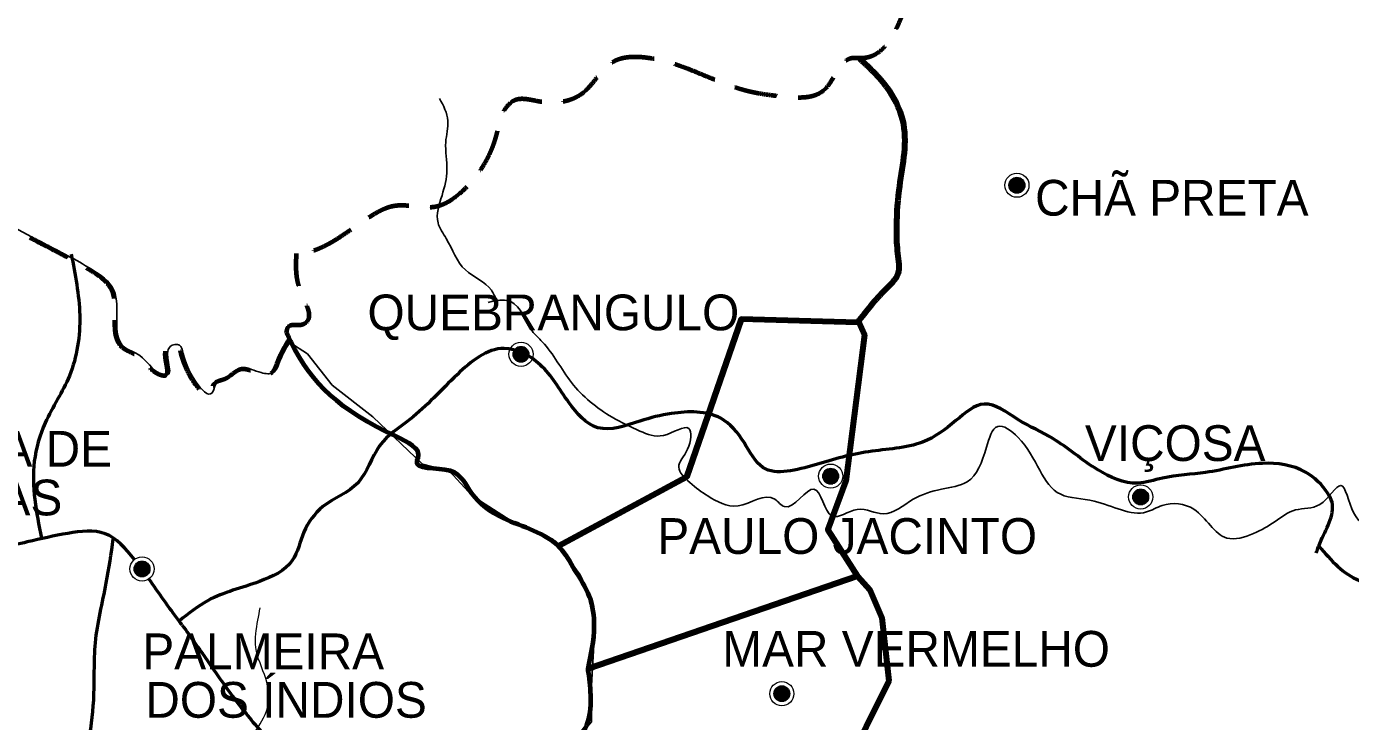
# Model space of a CAD drawing. Extents: x 512883 to 1063249, y 8784064 to 9081064.
# Drawn here: x 755485 to 811055, y 8952193 to 8981350 of the extents above; entities that cross this region are included whole.
import ezdxf

# ---------------------------------------------------------------- set-up
doc = ezdxf.new("R2010")
doc.units = 0
doc.header["$LTSCALE"] = 600
doc.linetypes.add('MEDIUM_DASHED', pattern=[4.5, 3, -1.5])
for name, color, linetype, lineweight in [('10', 7, 'Continuous', 53), ('13', 7, 'Continuous', 90), ('20', 7, 'Continuous', 53), ('5', 7, 'Continuous', 13), ('60', 7, 'Continuous', 25), ('7', 7, 'Continuous', 13)]:
    doc.layers.add(name, color=color, linetype=linetype, lineweight=lineweight)

msp = doc.modelspace()

# ---------------------------------------------------------------- linework, layer by layer
at = {"layer": '10'}
for points in [[(809616.9, 8959267.4), (809825.5, 8959797.2), (810249, 8961488.9), (810105.3, 8961759.7), (809170.8, 8962654), (807357.9, 8963023.8), (804970.4, 8962640.4), (803164.1, 8962405.1), (802121.3, 8962193), (800446.9, 8962751), (798563.3, 8964059.7), (797087.1, 8964868.8), (795673.1, 8965511.1), (794494.9, 8964818.7), (793098, 8963916.8), (790831.3, 8963513), (788586.3, 8962963.2), (786396.8, 8962851.7), (785601.5, 8963892.6), (784625.4, 8964912), (782553, 8965114), (781230, 8964796.7), (779464.4, 8964519.7), (778246.8, 8965580), (777043.4, 8967162.2), (775528.5, 8967845.9), (773570.9, 8966754.4), (771581.8, 8964869.9), (770307.8, 8963759.7), (769400.4, 8962212.5), (767924.2, 8961206.1), (767132.1, 8960139.2), (766642.8, 8958948.2), (765265.7, 8958067.2), (763103.9, 8957267.3), (761887.4, 8956407.7)], [(760025.4, 8958989.5), (758791.9, 8960070.6), (757224, 8960086.4), (755519.6, 8959726.1), (753291.3, 8959489.3), (750147.9, 8960209.6), (749997.5, 8960195.6)], [(760373.1, 8942504.5), (759520.9, 8943232.2), (758173.4, 8945126.8), (757857.6, 8946419.7), (757806.3, 8949236.7), (758306.2, 8953099), (758380.2, 8955499.1), (758834.8, 8958004.7), (759126.7, 8959859.4)], [(809734.3, 8959555), (811432, 8958112), (812579.6, 8957927.9), (814085.6, 8958058), (814804.3, 8958498.5), (816229.1, 8958691), (817376.8, 8958506.8), (818165.9, 8958029.4), (818881.1, 8956967.5), (819268.1, 8956509.6), (820335.8, 8956283.5), (821302.8, 8956077.9), (822492.5, 8955727), (823556.6, 8954019.2), (824559.4, 8952394.8), (826374, 8950063.4), (827121.3, 8946706.5), (827050.8, 8944306.1)], [(762022.2, 8956228.6), (761887.4, 8956407.7), (760623.2, 8958172.3)]]:
    msp.add_spline(points, degree=3, dxfattribs=at)
at = {"layer": '13'}
msp.add_line((790366.5, 8958294.4), (779053.8, 8954397.2), dxfattribs=at)
for points in [[(790369.3, 8968937.3), (785483.9, 8969067.6), (783185.5, 8962444.9), (777810.8, 8959546.7)], [(790399.5, 8968972.9), (790656.5, 8968416.5), (789880.2, 8962278.7), (789119.1, 8960231.1), (790366.5, 8958294.4), (790875.4, 8957711.7), (791390.8, 8956544.8), (791681.4, 8953895.4), (789774.1, 8950070.4), (790016.3, 8949759.2)]]:
    msp.add_lwpolyline(points, dxfattribs=at)
at = {"layer": '13', "lineweight": 25}
msp.add_lwpolyline([(787332.9, 8950099.2), (785823.8, 8950099.2), (783836.6, 8949815), (781186.9, 8949530.8), (779767.4, 8949720.3), (778537.2, 8949909.7), (777401.6, 8949909.7), (777874.8, 8950667.6), (778726.4, 8951614.9), (779199.6, 8952183.3), (779199.6, 8953699), (779294.2, 8955404.1), (779294.2, 8957014.5), (778726.4, 8958340.8), (777685.5, 8959761.7), (775982.1, 8960519.6), (774184.1, 8961656.3), (773237.8, 8962698.4), (772102.2, 8962982.6), (770020.3, 8964971.9), (768316.9, 8966298.1), (767276, 8967624.4), (766531.3, 8968098.7)], dxfattribs=at)
at = {"layer": '13', "linetype": 'MEDIUM_DASHED', "lineweight": 70}
for points in [[(794561.3, 8984247.3), (793616.3, 8984286), (792392.4, 8982278.7), (790528.1, 8980018.9), (790126.1, 8980017.6), (788955.1, 8978678.2), (787269.9, 8978401.5), (785639, 8978667.5), (783741.9, 8979370.9), (781684.8, 8980011.2), (780098.6, 8979860), (778786.9, 8978520.2), (777001.7, 8978201.4), (775996.1, 8978260.7), (775361.7, 8977465.7), (775246.4, 8976985.3), (773727.5, 8974392.8), (772648.9, 8973784.1), (770940.2, 8973820.3), (769920, 8973378.8), (768383.8, 8972351.3), (766882.2, 8971824.7), (766821.9, 8971824.5)], [(753258.6, 8973800.6), (756145, 8972228.3), (758126.6, 8971149.5), (759060.8, 8970276.1), (759489.1, 8967898.4), (760156.5, 8967525), (761008.9, 8966776.5), (761311.1, 8966714.8), (761418.5, 8967904.7), (761819.8, 8967968.6), (761964.4, 8967614.3), (763228, 8966032.4), (763365, 8966366.7), (763825, 8966576.9), (764463.7, 8966975.4), (765249.4, 8966811), (765751.8, 8966812.7), (766047.5, 8967335.3), (766506.4, 8968208.9)], [(766401.5, 8968517.5), (766493.8, 8968776.7), (767015.7, 8968841), (767255.5, 8968966.9), (767000.5, 8970218.2), (766821.9, 8971824.5)]]:
    msp.add_spline(points, degree=3, dxfattribs=at)
at = {"layer": '13'}
msp.add_spline([(790464.2, 8979989.1), (791688.7, 8978666.2), (792287.2, 8977249.1), (792096.9, 8974473), (791995.2, 8972761.4), (792045.8, 8971822.5), (792055.3, 8970966.9), (791539.9, 8970318.3), (790369.3, 8968937.3)], degree=3, dxfattribs=at)
at = {"layer": '13', "lineweight": 25}
msp.add_spline([(766531.3, 8968098.7), (766139.1, 8967352), (765843.4, 8966829.4), (765340.9, 8966827.7), (764555.2, 8966992.2), (763916.5, 8966593.6), (763456.6, 8966383.4), (763319.6, 8966049.1), (762055.9, 8967631), (761911.3, 8967985.3), (761510.1, 8967921.4), (761402.6, 8966731.5), (761100.5, 8966793.2), (760248, 8967541.7), (759580.7, 8967915.2), (759152.4, 8970292.8), (758218.2, 8971166.2), (756236.6, 8972245), (753350.1, 8973817.3)], degree=3, dxfattribs=at)
at = {"layer": '13', "lineweight": 70}
for points in [[(779053.8, 8954397.2), (779315.4, 8956192.7), (779120.9, 8957423.3), (778505.5, 8958548.2), (777872, 8959485.3), (775486.6, 8960729.7), (774168.7, 8961768.8), (773274, 8962705), (771882.4, 8963138.8), (771921.4, 8963243.2), (770966.7, 8964158.3), (766602, 8968088.4), (766401.5, 8968517.5)], [(777083.3, 8949780.2), (777094.8, 8949799.9), (777707.5, 8950740.9), (778940.6, 8951913.5), (779169.6, 8953020.3), (779097.1, 8954126.1), (779053.8, 8954397.2)]]:
    msp.add_spline(points, degree=3, dxfattribs=at)
at = {"layer": '20'}
for points in [[(757362.8, 8971798.3), (757718.1, 8969235), (757286.6, 8966697.4), (756271.3, 8964723.6), (755814.4, 8963108.8), (756109.2, 8959887.7)], [(762022.2, 8956228.6), (763065.5, 8954766.9), (764487.8, 8952789.5), (765663, 8951394.6), (767135.2, 8949600.3), (768531.3, 8947190.8), (769724.3, 8944935.2), (771450.3, 8942705.1), (774169.2, 8941219.5), (776144.1, 8941290.1)]]:
    msp.add_spline(points, degree=3, dxfattribs=at)
at = {"layer": '5'}
for p, q in [((796721.7, 8974699.1), (797386.5, 8974699.1)), ((796722.3, 8974669.1), (797386.2, 8974669.1)), ((796723.8, 8974729.1), (797384.4, 8974729.1)), ((796725.3, 8974639.1), (797382.9, 8974639.1)), ((796728.6, 8974759.1), (797379.6, 8974759.1)), ((796731.3, 8974609.1), (797376.9, 8974609.1)), ((796736.7, 8974789.1), (797371.5, 8974789.1)), ((796747.5, 8974819.1), (797360.7, 8974819.4)), ((796761.9, 8974849.1), (797346.6, 8974849.1)), ((796780.2, 8974879.1), (797328.3, 8974879.1)), ((796804.2, 8974909.1), (797304.6, 8974909.1)), ((796833.3, 8974939.1), (797274.9, 8974939.1)), ((796872.9, 8974969.1), (797235.3, 8974969.1)), ((796930.2, 8974999.1), (797178, 8974999.1)), ((796740.3, 8974579.1), (797367.9, 8974579.1)), ((796752.9, 8974549.1), (797355.6, 8974549.4)), ((796768.8, 8974519.1), (797339.4, 8974519.1)), ((796789.5, 8974489.1), (797319, 8974489.4)), ((796814.7, 8974458.8), (797293.8, 8974459.1)), ((796848, 8974429.1), (797260.2, 8974429.1)), ((796893, 8974399.1), (797215.2, 8974399.1)), ((796966.8, 8974369.1), (797141.1, 8974369.1)), ((775908.5, 8967607.6), (776573.2, 8967607.6)), ((775909.1, 8967577.6), (776573, 8967577.6)), ((775910.6, 8967637.6), (776571.2, 8967637.6)), ((775912.1, 8967547.6), (776569.7, 8967547.6)), ((775915.3, 8967667.6), (776566.3, 8967667.6)), ((775918.1, 8967517.6), (776563.7, 8967517.6)), ((775923.5, 8967697.6), (776558.2, 8967697.6)), ((775927.1, 8967487.6), (776554.7, 8967487.6)), ((775934.2, 8967727.6), (776547.5, 8967727.9)), ((775939.7, 8967457.6), (776542.3, 8967457.9)), ((775948.7, 8967757.6), (776533.3, 8967757.6)), ((775955.6, 8967427.6), (776526.2, 8967427.6)), ((775967, 8967787.6), (776515.1, 8967787.6)), ((775976.2, 8967397.6), (776505.8, 8967397.9)), ((775991, 8967817.6), (776491.3, 8967817.6)), ((776020.1, 8967847.6), (776461.7, 8967847.6)), ((776059.7, 8967877.6), (776422.1, 8967877.6)), ((776117, 8967907.6), (776364.8, 8967907.6)), ((776001.5, 8967367.3), (776480.6, 8967367.6)), ((776034.8, 8967337.6), (776447, 8967337.6)), ((776079.8, 8967307.6), (776402, 8967307.6)), ((776153.6, 8967277.6), (776327.8, 8967277.6)), ((788905.1, 8962495.8), (789569.9, 8962495.8)), ((788905.7, 8962465.8), (789569.6, 8962465.8)), ((788907.2, 8962525.8), (789567.8, 8962525.8)), ((788908.7, 8962435.8), (789566.3, 8962435.8)), ((788912, 8962555.8), (789563, 8962555.8)), ((788914.7, 8962405.8), (789560.3, 8962405.8)), ((788920.1, 8962585.8), (789554.9, 8962585.8)), ((788930.9, 8962615.8), (789544.1, 8962616.1)), ((788945.3, 8962645.8), (789530, 8962645.8)), ((788963.6, 8962675.8), (789511.7, 8962675.8)), ((788987.6, 8962705.8), (789488, 8962705.8)), ((789016.7, 8962735.8), (789458.3, 8962735.8)), ((789056.3, 8962765.8), (789418.7, 8962765.8)), ((789113.6, 8962795.8), (789361.4, 8962795.8)), ((788923.7, 8962375.8), (789551.3, 8962375.8)), ((788936.3, 8962345.8), (789539, 8962346.1)), ((788952.2, 8962315.8), (789522.8, 8962315.8)), ((788972.9, 8962285.8), (789502.4, 8962286.1)), ((788998.1, 8962255.5), (789477.2, 8962255.8)), ((789031.4, 8962225.8), (789443.6, 8962225.8)), ((789076.4, 8962195.8), (789398.6, 8962195.8)), ((789150.2, 8962165.8), (789324.5, 8962165.8)), ((801999.5, 8961832.5), (802499.8, 8961832.5)), ((802028.6, 8961862.5), (802470.2, 8961862.5)), ((802068.2, 8961892.5), (802430.6, 8961892.5)), ((802125.5, 8961922.5), (802373.2, 8961922.5)), ((801917, 8961622.5), (802581.8, 8961622.5)), ((801917.6, 8961592.5), (802581.5, 8961592.5)), ((801919.1, 8961652.5), (802579.7, 8961652.5)), ((801920.6, 8961562.5), (802578.2, 8961562.5)), ((801923.8, 8961682.5), (802574.8, 8961682.5)), ((801926.6, 8961532.5), (802572.2, 8961532.5)), ((801932, 8961712.5), (802566.8, 8961712.5)), ((801935.6, 8961502.5), (802563.2, 8961502.5)), ((801942.8, 8961742.5), (802556, 8961742.8)), ((801948.2, 8961472.5), (802550.8, 8961472.8)), ((801957.2, 8961772.5), (802541.8, 8961772.5)), ((801964.1, 8961442.5), (802534.7, 8961442.5)), ((801975.5, 8961802.5), (802523.6, 8961802.5)), ((801984.8, 8961412.5), (802514.2, 8961412.8)), ((802010, 8961382.2), (802489.1, 8961382.5)), ((802043.2, 8961352.5), (802455.5, 8961352.5)), ((802088.2, 8961322.5), (802410.5, 8961322.5)), ((802162.1, 8961292.5), (802336.3, 8961292.5)), ((760002.6, 8958602.3), (760667.4, 8958602.3)), ((760003.2, 8958572.3), (760667.1, 8958572.3)), ((760004.7, 8958632.3), (760665.3, 8958632.3)), ((760006.2, 8958542.3), (760663.8, 8958542.3)), ((760009.5, 8958662.3), (760660.5, 8958662.3)), ((760012.2, 8958512.3), (760657.8, 8958512.3)), ((760017.6, 8958692.3), (760652.4, 8958692.3)), ((760028.4, 8958722.3), (760641.6, 8958722.6)), ((760042.8, 8958752.3), (760627.5, 8958752.3)), ((760061.1, 8958782.3), (760609.2, 8958782.3)), ((760085.1, 8958812.3), (760585.5, 8958812.3)), ((760114.2, 8958842.3), (760555.8, 8958842.3)), ((760153.8, 8958872.3), (760516.2, 8958872.3)), ((760211.1, 8958902.3), (760458.9, 8958902.3)), ((760021.2, 8958482.3), (760648.8, 8958482.3)), ((760033.8, 8958452.3), (760636.5, 8958452.6)), ((760049.7, 8958422.3), (760620.3, 8958422.3)), ((760070.4, 8958392.3), (760599.9, 8958392.6)), ((760095.6, 8958362), (760574.7, 8958362.3)), ((760128.9, 8958332.3), (760541.1, 8958332.3)), ((760173.9, 8958302.3), (760496.1, 8958302.3)), ((760247.7, 8958272.3), (760422, 8958272.3)), ((786881.3, 8953489.7), (787494.5, 8953490)), ((786895.7, 8953519.7), (787480.4, 8953519.7)), ((786914, 8953549.7), (787462.1, 8953549.7)), ((786938, 8953579.7), (787438.4, 8953579.7)), ((786967.1, 8953609.7), (787408.7, 8953609.7)), ((787006.7, 8953639.7), (787369.1, 8953639.7)), ((787064, 8953669.7), (787311.8, 8953669.7)), ((786855.5, 8953369.7), (787520.3, 8953369.7)), ((786856.1, 8953339.7), (787520, 8953339.7)), ((786857.6, 8953399.7), (787518.2, 8953399.7)), ((786859.1, 8953309.7), (787516.7, 8953309.7)), ((786862.4, 8953429.7), (787513.4, 8953429.7)), ((786865.1, 8953279.7), (787510.7, 8953279.7)), ((786870.5, 8953459.7), (787505.3, 8953459.7)), ((786874.1, 8953249.7), (787501.7, 8953249.7)), ((786886.7, 8953219.7), (787489.4, 8953220)), ((786902.6, 8953189.7), (787473.2, 8953189.7)), ((786923.3, 8953159.7), (787452.8, 8953160)), ((786948.5, 8953129.4), (787427.6, 8953129.7)), ((786981.8, 8953099.7), (787394, 8953099.7)), ((787026.8, 8953069.7), (787349, 8953069.7)), ((787100.6, 8953039.7), (787274.9, 8953039.7))]:
    msp.add_line(p, q, dxfattribs=at)
for centre, radius in [((797054.2, 8974690.1), 506.1), ((797054.2, 8974690.1), 332.9), ((776240.9, 8967598.6), 506.1), ((776240.9, 8967598.6), 332.9), ((789237.6, 8962486.8), 506.1), ((789237.6, 8962486.8), 332.9), ((802249.4, 8961613.5), 506.1), ((802249.4, 8961613.5), 332.9), ((760335.1, 8958593.3), 506.1), ((760335.1, 8958593.3), 332.9), ((787188, 8953360.7), 506.1), ((787188, 8953360.7), 332.9)]:
    msp.add_circle(centre, radius, dxfattribs=at)
at = {"layer": '60'}
for points in [[(928828.8, 9027989.5), (927727.3, 9017705.9), (905698.2, 8975836.8), (863108.4, 8926255), (823455.9, 8876673.2), (798489.5, 8846556.8), (787107.7, 8828193.2)], [(928828.8, 9027989.5), (927727.3, 9017705.9), (905698.2, 8975836.8), (863108.4, 8926255), (823455.9, 8876673.2), (798489.5, 8846556.8), (787107.7, 8828193.2)], [(775215.3, 8969867.5), (774999, 8970285.8), (773904.2, 8971137.9), (773105.9, 8972450), (772756.8, 8973116.6), (772925, 8974265), (773134.3, 8975329.9), (773081.2, 8976498.4), (773171.7, 8977396), (772819.7, 8978333.9)], [(818100.3, 8958307.5), (816732.1, 8958650.8), (814661, 8958727.6), (813018.1, 8958263.2), (811642.4, 8959072.6), (811814.1, 8959907.9), (811199.8, 8960928.5), (810644.2, 8962095.3), (809768.7, 8961299.5), (808746.2, 8961066.7), (807887.3, 8960583.9), (806988.5, 8960080.2), (805865.1, 8959888.7), (804485, 8961094.6), (803156.7, 8961257.3), (802496.5, 8960983.9), (800300.7, 8961435.9), (798890.6, 8961723.5), (797095.4, 8964117.5), (796246.2, 8964573.9), (795773.6, 8963695.9), (794965.5, 8962253.4), (793883.7, 8961936.8), (792702.5, 8961515.7), (791443, 8960906.4), (790355.7, 8961090.7), (789293.5, 8960816), (788537.4, 8961940.5), (787299.4, 8961206.1), (786894, 8961517.8), (785349.4, 8961241.5), (784078.6, 8961654.8), (783328.8, 8962215.8), (782859.3, 8962861.2), (783232.9, 8963613.7), (783283.5, 8964490.3), (782221.5, 8964194.7), (781234.7, 8964379.3), (780062.5, 8964959.8), (778358.1, 8966415.1), (777133.3, 8968122.4), (776706.2, 8968580.1), (775808.2, 8969808.4), (775064.4, 8969826.9), (774860.3, 8969768.4)]]:
    msp.add_spline(points, degree=3, dxfattribs=at)
at = {"layer": '60', "lineweight": 13}
msp.add_spline([(761930.5, 8946052.6), (762027.4, 8946763.3), (762062.9, 8947262.6), (762482.1, 8947680), (763020.7, 8948243.3), (763432.6, 8949409.5), (763747.6, 8950180.1), (764386.5, 8950785.3), (765042.7, 8951702.7), (765596.6, 8952765.3), (765524.3, 8953992.4), (765108.6, 8955301.8), (765198.3, 8956446.2), (765294.1, 8956966.6)], degree=3, dxfattribs=at)
at = {"layer": '7', "lineweight": 25}
for points in [[(775215.3, 8969867.5), (774999, 8970285.8), (773904.2, 8971137.9), (773105.9, 8972450), (772756.8, 8973116.6), (772925, 8974265), (773134.3, 8975329.9), (773081.2, 8976498.4), (773171.7, 8977396), (772819.7, 8978333.9)], [(818100.3, 8958307.5), (816732.1, 8958650.8), (814661, 8958727.6), (813018.1, 8958263.2), (811642.4, 8959072.6), (811814.1, 8959907.9), (811199.8, 8960928.5), (810644.2, 8962095.3), (809768.7, 8961299.5), (808746.2, 8961066.7), (807887.3, 8960583.9), (806988.5, 8960080.2), (805865.1, 8959888.7), (804485, 8961094.6), (803156.7, 8961257.3), (802496.5, 8960983.9), (800300.7, 8961435.9), (798890.6, 8961723.5), (797095.4, 8964117.5), (796246.2, 8964573.9), (795773.6, 8963695.9), (794965.5, 8962253.4), (793883.7, 8961936.8), (792702.5, 8961515.7), (791443, 8960906.4), (790355.7, 8961090.7), (789293.5, 8960816), (788537.4, 8961940.5), (787299.4, 8961206.1), (786894, 8961517.8), (785349.4, 8961241.5), (784078.6, 8961654.8), (783328.8, 8962215.8), (782859.3, 8962861.2), (783232.9, 8963613.7), (783283.5, 8964490.3), (782221.5, 8964194.7), (781234.7, 8964379.3), (780062.5, 8964959.8), (778358.1, 8966415.1), (777133.3, 8968122.4), (776706.2, 8968580.1), (775808.2, 8969808.4), (775064.4, 8969826.9), (774860.3, 8969768.4)]]:
    msp.add_spline(points, degree=3, dxfattribs=at)
at = {"layer": '7'}
msp.add_spline([(761930.5, 8946052.6), (762027.4, 8946763.3), (762062.9, 8947262.6), (762482.1, 8947680), (763020.7, 8948243.3), (763432.6, 8949409.5), (763747.6, 8950180.1), (764386.5, 8950785.3), (765042.7, 8951702.7), (765596.6, 8952765.3), (765524.3, 8953992.4), (765108.6, 8955301.8), (765198.3, 8956446.2), (765294.1, 8956966.6)], degree=3, dxfattribs=at)

# ---------------------------------------------------------------- texts
at = {"layer": '5'}
for s, p in [('CHÃ PRETA', (797815.6, 8973414.4)), ('QUEBRANGULO', (769796.3, 8968604)), ('VIÇOSA', (799907, 8963121.4)), ('ESTRELA DE', (746590.3, 8962884.2)), ('ALAGOAS', (747400.9, 8960840.2)), ('PAULO JACINTO', (781961.8, 8959223.7)), ('PALMEIRA ', (760348.3, 8954385.5)), ('MAR VERMELHO', (784687.5, 8954491.6)), ('DOS ÍNDIOS', (760473.3, 8952351.3))]:
    msp.add_text(s, height=1500, dxfattribs=at).set_placement(p)

doc.saveas('drawing.dxf')
